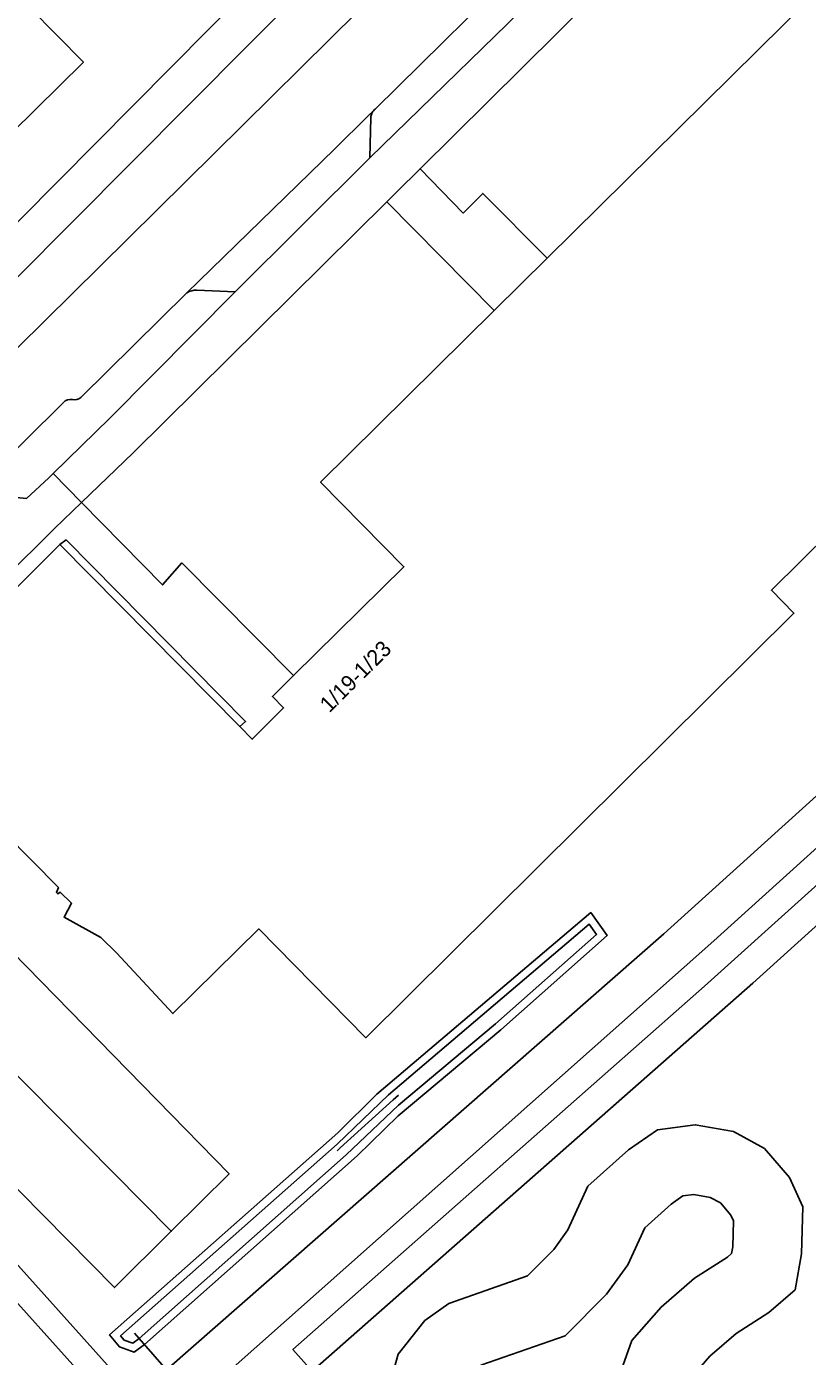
# Model space of a CAD drawing. Extents: x 162788 to 163838, y 385791 to 386523.
# Drawn here: x 163008.9 to 163058.2, y 385931.9 to 386015.9 of the extents above; entities that cross this region are included whole.
import ezdxf

# ---------------------------------------------------------------- set-up
doc = ezdxf.new("R2010")
doc.units = 0
for name, color, linetype in [('IMGEO_Berm_groen', 7, 'Continuous'), ('IMGEO_Duiker', 7, 'Continuous'), ('IMGEO_Erf', 7, 'Continuous'), ('IMGEO_Grasland_overig', 7, 'Continuous'), ('IMGEO_Meer_plas_ven_vijver', 7, 'Continuous'), ('IMGEO_Oever', 7, 'Continuous'), ('IMGEO_Pand', 7, 'Continuous'), ('IMGEO_Pand_nummerreeks', 7, 'Continuous'), ('IMGEO_Parkeervlak_open', 7, 'Continuous'), ('IMGEO_Rijbaan_lokaal_open', 7, 'Continuous'), ('IMGEO_Voetpad_halfverhard', 7, 'Continuous'), ('IMGEO_Voetpad_open', 7, 'Continuous'), ('IMGEO_Waterloop', 7, 'Continuous'), ('IMGEO_Woonerf_gesloten', 7, 'Continuous'), ('IMGEO_Woonerf_open', 7, 'Continuous')]:
    doc.layers.add(name, color=color, linetype=linetype)

msp = doc.modelspace()

# ---------------------------------------------------------------- linework, layer by layer
at = {"layer": 'IMGEO_Berm_groen'}
for points in [[(163037.097, 386024.076), (163037.572, 386024.546), (163037.56, 386024.557), (163035.844, 386026.06), (163035.711, 386026.125), (163035.573, 386026.179), (163035.431, 386026.22), (163035.286, 386026.249), (163035.139, 386026.265), (163034.991, 386026.269), (163034.844, 386026.26), (163034.697, 386026.239), (163034.553, 386026.205), (163034.413, 386026.159), (163034.276, 386026.101), (163034.146, 386026.031), (163034.022, 386025.951), (163033.905, 386025.86), (163000.759, 385992.514), (163001.163, 385990.386), (163002.722, 385990.111), (163003.107, 385990.494), (163013.512, 386000.753)], [(163042.44, 386019.195), (163041.15, 386020.839), (163040.955, 386020.636), (163030.909, 386010.698), (163030.859, 386010.653), (163030.812, 386010.603), (163030.77, 386010.55), (163030.734, 386010.493), (163030.702, 386010.434), (163030.676, 386010.371), (163030.656, 386010.306), (163030.641, 386010.24), (163030.633, 386010.173), (163030.584, 386007.63)]]:
    msp.add_lwpolyline(points, close=True, dxfattribs=at)
for points in [[(163007.834, 385986.192), (163008.884, 385986.101), (163010.278, 385987.398), (163010.562, 385987.676), (163014.137, 385991.175), (163022.063, 385999.154)], [(163019.018, 385999.096), (163012.301, 385992.486)], [(163022.063, 385999.154), (163019.64, 385999.258)], [(163011.206, 385992.166), (163006.309, 385987.307), (163006.258, 385987.257), (163006.735, 385986.756)]]:
    msp.add_lwpolyline(points, dxfattribs=at)
for centre, radius, start, end in [((163019.588, 385998.183), 1.076, 87.22469, 121.97206), ((163011.651, 385991.763), 0.6, 77.9532, 137.82769), ((163011.916, 385992.891), 0.559, 255.49135, 313.55484)]:
    msp.add_arc(centre, radius, start, end, dxfattribs=at)
at = {"layer": 'IMGEO_Duiker'}
for points in [[(163032.385, 385948.389), (163032.059, 385948.093), (163028.707, 385945.049), (163028.513, 385944.873)], [(163021.036, 385927.241), (163020.743, 385927.576), (163019.493, 385929.004), (163017.729, 385931.02), (163016.002, 385932.994), (163015.7, 385933.339)]]:
    msp.add_lwpolyline(points, dxfattribs=at)
at = {"layer": 'IMGEO_Erf'}
for points in [[(162996.592, 385991.771), (163032.285, 386027.77), (163032.418, 386027.879), (163032.54, 386028), (163032.652, 386028.132), (163032.751, 386028.272), (163032.837, 386028.421), (163032.91, 386028.577), (163032.969, 386028.739), (163033.013, 386028.905), (163033.042, 386029.075), (163033.057, 386029.246), (163033.056, 386029.418), (163033.04, 386029.59), (163033.008, 386029.759), (163032.962, 386029.925), (163032.902, 386030.086), (163032.827, 386030.241), (163032.739, 386030.389), (163032.639, 386030.529), (163032.526, 386030.659), (163032.402, 386030.778), (163011.849, 386051.6), (162989.767, 386074.455)], [(163017.319, 385930.66), (163017.729, 385931.02), (163049.154, 385958.577), (163094.983, 386000), (163117.539, 386020.387), (163122.643, 386025)], [(163007.393, 386018.836), (163012.476, 386013.665), (163001.892, 386003.263)], [(163096.492, 386017.373), (163085.965, 386006.999), (163084.541, 386008.445), (163080.808, 386004.766), (163082.232, 386003.32), (163061.136, 385982.53), (163059.705, 385983.984), (163055.956, 385980.293), (163057.387, 385978.839), (163030.332, 385952.014), (163023.562, 385958.891), (163018.125, 385953.54), (163014.586, 385957.351), (163013.576, 385958.346), (163011.253, 385959.626), (163011.721, 385960.514), (163010.996, 385961.219), (163010.861, 385961.104), (163010.77, 385961.201), (163010.895, 385961.518), (163007.528, 385964.926)], [(163002.454, 385963.068), (163021.685, 385943.414), (163018.027, 385939.782), (163014.444, 385936.225), (163008.474, 385942.282)], [(163006.158, 385940.036), (163015.063, 385930.12)]]:
    msp.add_lwpolyline(points, dxfattribs=at)
for points in [[(163061.746, 386020.997), (163058.142, 386024.659), (163065.054, 386031.485), (163068.699, 386027.817), (163077.495, 386036.498), (163076.937, 386037.062), (163076.555, 386036.707), (163076.343, 386036.894), (163075.467, 386036.004), (163071.974, 386039.437), (163072.8, 386040.377), (163073.83, 386041.473), (163073.15, 386042.156), (163074.556, 386043.508), (163072.634, 386045.307), (163059.673, 386032.606), (163033.75, 386006.932), (163036.486, 386004.135), (163037.717, 386005.376), (163041.793, 386001.29)], [(163038.444, 385997.982), (163031.641, 386004.843), (163015.617, 385988.98), (163012.357, 385985.846), (163017.472, 385980.633), (163018.703, 385982.023), (163025.759, 385974.902), (163032.735, 385981.78), (163027.461, 385987.135)], [(163022.35, 385971.68), (163022.722, 385971.996), (163011.379, 385983.478), (163010.977, 385983.178)], [(163029.78, 385944.559), (163016.333, 385932.616), (163015.689, 385932.138), (163014.745, 385932.476), (163014.128, 385933.232), (163028.553, 385946.006), (163031.02, 385948.437), (163044.539, 385959.921), (163045.578, 385958.468), (163038.857, 385952.519), (163032.361, 385947.069)]]:
    msp.add_lwpolyline(points, close=True, dxfattribs=at)
at = {"layer": 'IMGEO_Grasland_overig'}
for points in [[(163124.87, 386022.725), (163124.372, 386023.234), (163119.271, 386018.624), (163098.66, 386000), (163052.327, 385958.135), (163019.493, 385929.004)], [(163014.02, 385928.88), (163004.992, 385938.906), (163001.097, 385935.129), (162993.271, 385943.2), (162987.265, 385949.393), (162990.415, 385952.447), (162984.93, 385958.104), (162984.824, 385958.213), (162984.994, 385958.379), (162983.584, 385959.834), (162983.683, 385959.93), (162982.321, 385961.335), (162982.74, 385961.741), (162981.364, 385963.159), (162980.713, 385967.362), (162978.82, 385965.396), (162976.126, 385962.358), (162975.572, 385961.559), (162975.149, 385959.464), (162975.37, 385957.61), (162975.637, 385957.589), (162979.899, 385961.798), (162986.21, 385955.407), (162954.255, 385923.851)], [(163031.501, 385928.933), (163032.364, 385932.011), (163034.061, 385934.14), (163035.568, 385935.218), (163040.535, 385936.967), (163042.203, 385938.635), (163043.095, 385939.872), (163044.36, 385942.634), (163046.92, 385944.936), (163048.76, 385946.201), (163051.148, 385946.518), (163053.563, 385946.086), (163055.519, 385945.022), (163057.101, 385943.181), (163057.949, 385941.318), (163057.863, 385938.355), (163057.46, 385936.082), (163055.792, 385934.644), (163053.722, 385933.32), (163052.068, 385931.889), (163050.963, 385930.626)]]:
    msp.add_lwpolyline(points, dxfattribs=at)
msp.add_lwpolyline([(163026.923, 385930.93), (163025.717, 385932.302), (163051.725, 385955.263), (163101.402, 386000), (163104.22, 386002.526), (163120.249, 386015.801), (163121.524, 386014.336), (163104.071, 386000), (163054.793, 385955.466)], close=True, dxfattribs=at)
at = {"layer": 'IMGEO_Meer_plas_ven_vijver'}
msp.add_lwpolyline([(163045.218, 385927.482), (163047.131, 385932.871), (163048.984, 385934.99), (163051.106, 385936.825), (163053.179, 385938.151), (163053.436, 385938.372), (163053.512, 385938.801), (163053.559, 385940.432), (163053.388, 385940.809), (163052.732, 385941.572), (163052.099, 385941.916), (163051.049, 385942.104), (163050.37, 385942.014), (163049.626, 385941.502), (163047.95, 385939.995), (163046.883, 385937.667), (163045.536, 385935.799), (163042.919, 385933.181), (163037.602, 385931.309)], dxfattribs=at)
at = {"layer": 'IMGEO_Oever'}
for points in [[(163029.78, 385944.559), (163032.361, 385947.069), (163038.857, 385952.519), (163045.578, 385958.468), (163044.539, 385959.921), (163031.02, 385948.437), (163028.553, 385946.006), (163014.128, 385933.232), (163014.745, 385932.476), (163015.689, 385932.138), (163016.333, 385932.616)], [(163032.394, 385947.752), (163029.08, 385944.609), (163016.002, 385932.994), (163015.606, 385932.701), (163015.046, 385932.902), (163014.822, 385933.176), (163028.502, 385945.29), (163031.756, 385948.403), (163044.448, 385959.185), (163044.906, 385958.544), (163038.529, 385952.899)]]:
    msp.add_lwpolyline(points, close=True, dxfattribs=at)
for points in [[(163050.963, 385930.626), (163052.068, 385931.889), (163053.722, 385933.32), (163055.792, 385934.644), (163057.46, 385936.082), (163057.863, 385938.355), (163057.949, 385941.318), (163057.101, 385943.181), (163055.519, 385945.022), (163053.563, 385946.086), (163051.148, 385946.518), (163048.76, 385946.201), (163046.92, 385944.936), (163044.36, 385942.634), (163043.095, 385939.872), (163042.203, 385938.635), (163040.535, 385936.967), (163035.568, 385935.218), (163034.061, 385934.14), (163032.364, 385932.011), (163031.501, 385928.933)], [(163037.602, 385931.309), (163042.919, 385933.181), (163045.536, 385935.799), (163046.883, 385937.667), (163047.95, 385939.995), (163049.626, 385941.502), (163050.37, 385942.014), (163051.049, 385942.104), (163052.099, 385941.916), (163052.732, 385941.572), (163053.388, 385940.809), (163053.559, 385940.432), (163053.512, 385938.801), (163053.436, 385938.372), (163053.179, 385938.151), (163051.106, 385936.825), (163048.984, 385934.99), (163047.131, 385932.871), (163045.218, 385927.482)]]:
    msp.add_lwpolyline(points, dxfattribs=at)
at = {"layer": 'IMGEO_Pand'}
for points in [[(163061.746, 386020.997), (163041.793, 386001.29), (163038.444, 385997.982), (163027.461, 385987.135), (163032.735, 385981.78), (163025.759, 385974.902), (163024.418, 385973.58), (163025.125, 385972.862), (163023.14, 385970.882), (163022.35, 385971.68), (163010.977, 385983.178), (163004.844, 385977.104)], [(163001.892, 386003.263), (163012.476, 386013.665), (163007.393, 386018.836)], [(163007.528, 385964.926), (163010.895, 385961.518), (163010.77, 385961.201), (163010.861, 385961.104), (163010.996, 385961.219), (163011.721, 385960.514), (163011.253, 385959.626), (163013.576, 385958.346), (163014.586, 385957.351), (163018.125, 385953.54), (163023.562, 385958.891), (163030.332, 385952.014), (163057.387, 385978.839), (163055.956, 385980.293), (163059.705, 385983.984), (163061.136, 385982.53), (163082.232, 386003.32), (163080.808, 386004.766), (163084.541, 386008.445), (163085.965, 386006.999), (163096.492, 386017.373)]]:
    msp.add_lwpolyline(points, dxfattribs=at)
at = {"layer": 'IMGEO_Parkeervlak_open'}
for points in [[(163030.584, 386007.63), (163030.633, 386010.173), (163030.641, 386010.24), (163030.656, 386010.306), (163030.676, 386010.371), (163030.702, 386010.434), (163030.734, 386010.493), (163030.77, 386010.55), (163030.812, 386010.603), (163030.48, 386010.274), (163028.349, 386008.165), (163019.018, 385999.096)], [(163019.64, 385999.258), (163022.063, 385999.154), (163030.584, 386007.63)]]:
    msp.add_lwpolyline(points, dxfattribs=at)
msp.add_lwpolyline([(162998.1, 385959.899), (162994.734, 385956.589), (162994.551, 385956.409), (163000, 385950.88), (163008.474, 385942.282), (163014.444, 385936.225), (163018.027, 385939.782)], close=True, dxfattribs=at)
msp.add_arc((163019.588, 385998.183), 1.076, 87.22469, 121.97206, dxfattribs=at)
at = {"layer": 'IMGEO_Rijbaan_lokaal_open'}
msp.add_lwpolyline([(163002.454, 385963.068), (162996.672, 385968.977), (162999.894, 385972.203), (163004.844, 385977.104), (163010.977, 385983.178), (163011.379, 385983.478), (163022.722, 385971.996), (163022.35, 385971.68), (163023.14, 385970.882), (163025.125, 385972.862), (163024.418, 385973.58), (163025.759, 385974.902), (163018.703, 385982.023), (163017.472, 385980.633), (163012.357, 385985.846), (163010.638, 385984.193), (163004.176, 385977.794), (162999.069, 385972.737), (162994.484, 385968.27), (162989.817, 385968.261), (162998.1, 385959.899), (163018.027, 385939.782), (163021.685, 385943.414)], close=True, dxfattribs=at)
at = {"layer": 'IMGEO_Voetpad_halfverhard'}
for points in [[(163098.66, 386000), (163119.271, 386018.624), (163124.372, 386023.234), (163122.643, 386025), (163117.539, 386020.387), (163094.983, 386000), (163049.154, 385958.577), (163017.729, 385931.02), (163017.319, 385930.66)], [(163015.063, 385930.12), (163006.158, 385940.036), (163004.992, 385938.906), (163014.02, 385928.88), (163014.753, 385928.066), (163010.512, 385924.235), (163011.775, 385922.307), (163013.336, 385918.64), (163014.613, 385915.642), (163018.115, 385918.075), (163016.588, 385921.548), (163015.103, 385924.926), (163016.555, 385926.064), (163019.493, 385929.004), (163052.327, 385958.135), (163098.66, 386000)]]:
    msp.add_lwpolyline(points, dxfattribs=at)
at = {"layer": 'IMGEO_Voetpad_open'}
msp.add_lwpolyline([(163033.75, 386006.932), (163032.291, 386005.487), (163031.641, 386004.843), (163038.444, 385997.982), (163041.793, 386001.29), (163037.717, 386005.376), (163036.486, 386004.135)], close=True, dxfattribs=at)
at = {"layer": 'IMGEO_Waterloop'}
for points in [[(163054.793, 385955.466), (163104.071, 386000), (163121.524, 386014.336), (163120.249, 386015.801), (163104.22, 386002.526), (163101.402, 386000), (163051.725, 385955.263), (163025.717, 385932.302), (163026.923, 385930.93)], [(163032.394, 385947.752), (163038.529, 385952.899), (163044.906, 385958.544), (163044.448, 385959.185), (163031.756, 385948.403), (163028.502, 385945.29), (163014.822, 385933.176), (163015.046, 385932.902), (163015.606, 385932.701), (163016.002, 385932.994), (163029.08, 385944.609)]]:
    msp.add_lwpolyline(points, close=True, dxfattribs=at)
at = {"layer": 'IMGEO_Woonerf_gesloten'}
for points in [[(162989.767, 386074.455), (163011.849, 386051.6), (163032.402, 386030.778), (163032.526, 386030.659), (163032.639, 386030.529), (163032.739, 386030.389), (163032.827, 386030.241), (163032.902, 386030.086), (163032.962, 386029.925), (163033.008, 386029.759), (163033.04, 386029.59), (163033.056, 386029.418), (163033.057, 386029.246), (163033.042, 386029.075), (163033.013, 386028.905), (163032.969, 386028.739), (163032.91, 386028.577), (163032.837, 386028.421), (163032.751, 386028.272), (163032.652, 386028.132), (163032.54, 386028), (163032.418, 386027.879), (163032.285, 386027.77), (162996.592, 385991.771)], [(163042.44, 386019.195), (163030.584, 386007.63), (163022.063, 385999.154), (163014.137, 385991.175), (163010.562, 385987.676), (163012.357, 385985.846), (163015.617, 385988.98), (163031.641, 386004.843), (163032.291, 386005.487), (163033.75, 386006.932), (163059.673, 386032.606)], [(163000.759, 385992.514), (163033.905, 386025.86)], [(162979.738, 385969.089), (162981.297, 385968.564), (162981.775, 385968.483), (162982.93, 385968.287), (162986.636, 385968.273), (162989.817, 385968.261), (162994.484, 385968.27), (162999.069, 385972.737), (163004.176, 385977.794), (163010.638, 385984.193), (163012.357, 385985.846), (163010.562, 385987.676), (163010.278, 385987.398), (163008.884, 385986.101), (163007.834, 385986.192)]]:
    msp.add_lwpolyline(points, dxfattribs=at)
at = {"layer": 'IMGEO_Woonerf_open'}
for points in [[(163028.349, 386008.165), (163030.48, 386010.274), (163030.812, 386010.603), (163030.859, 386010.653), (163030.909, 386010.698), (163040.955, 386020.636), (163041.15, 386020.839), (163041.212, 386020.904), (163037.572, 386024.546), (163037.097, 386024.076), (163013.512, 386000.753), (163003.107, 385990.494), (163006.309, 385987.307), (163011.206, 385992.166)], [(163012.301, 385992.486), (163019.018, 385999.096), (163028.349, 386008.165)]]:
    msp.add_lwpolyline(points, dxfattribs=at)
for centre, radius, start, end in [((163011.651, 385991.763), 0.6, 77.9532, 137.82769), ((163011.916, 385992.891), 0.559, 255.49135, 313.55484)]:
    msp.add_arc(centre, radius, start, end, dxfattribs=at)

# ---------------------------------------------------------------- texts
at = {"layer": 'IMGEO_Pand_nummerreeks'}
msp.add_text('1/19-1/23', height=1, rotation=44.87405, dxfattribs=at).set_placement((163028.016, 385972.508))

doc.saveas('drawing.dxf')
